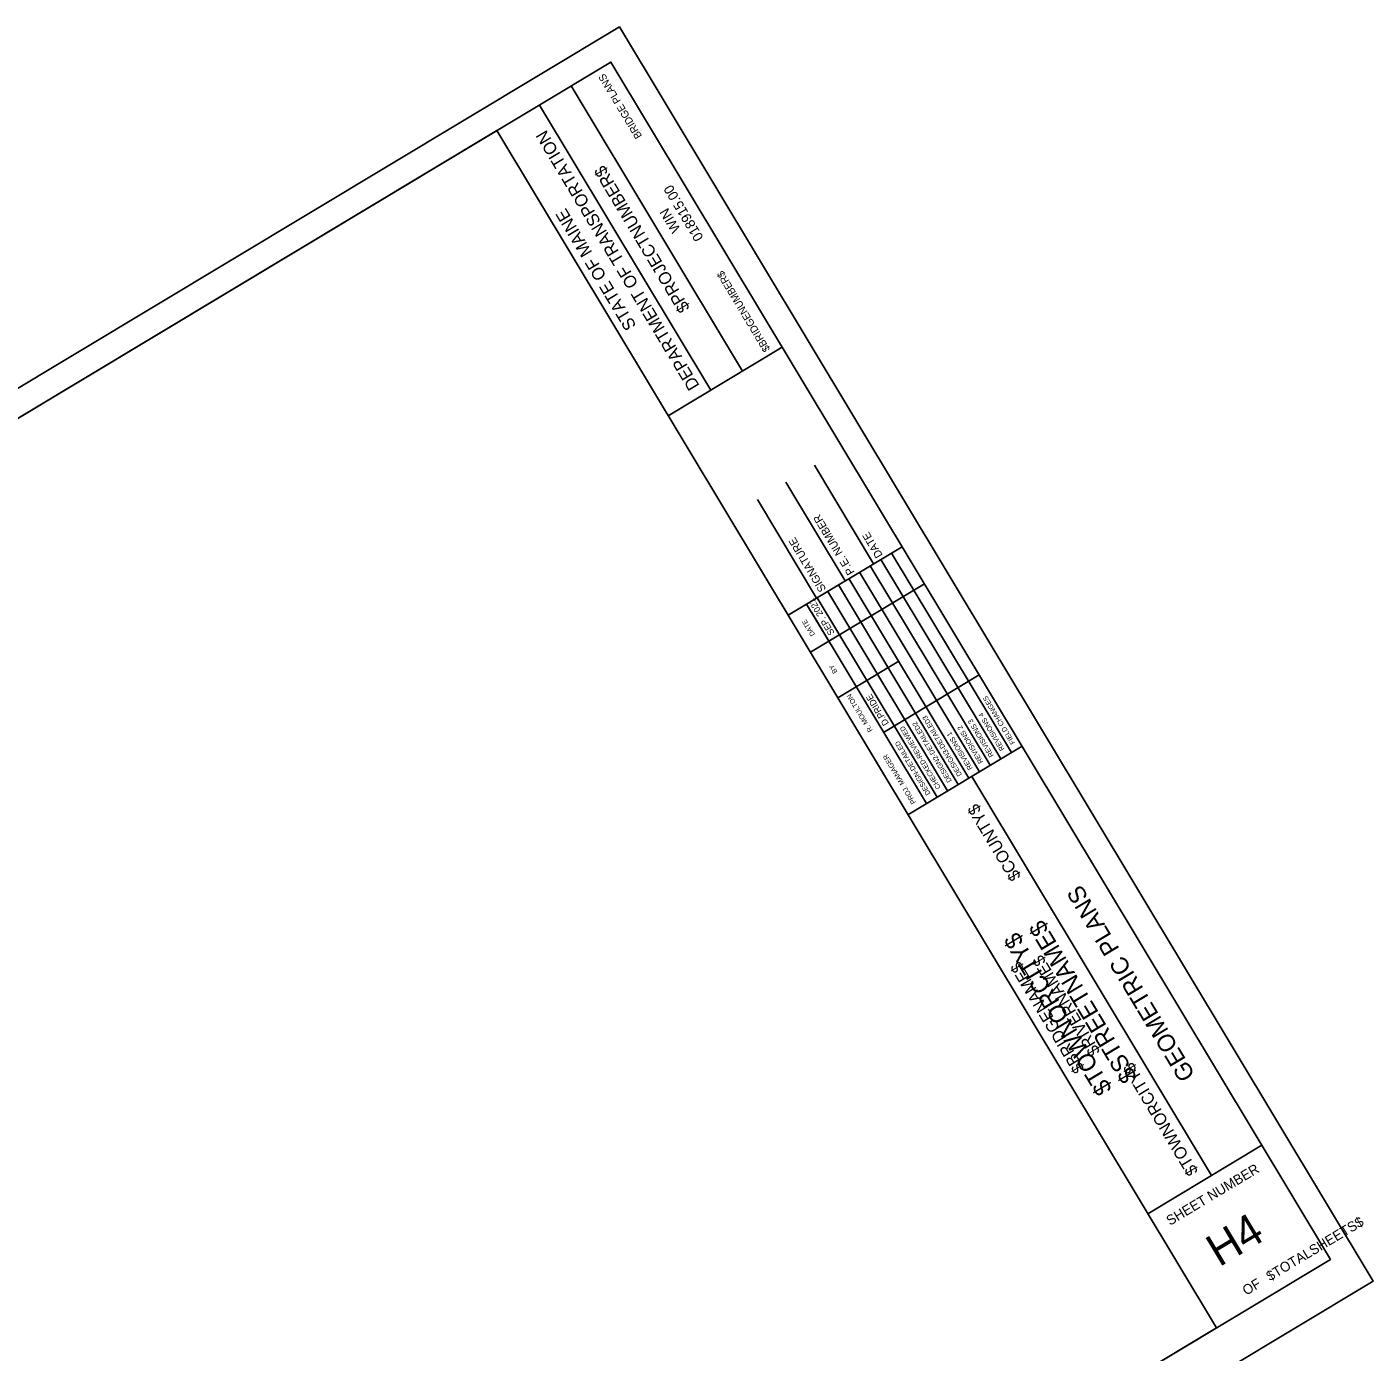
# Model space of a CAD drawing. Extents: x 1743892 to 1744904, y 462604 to 463513.
# Drawn here: x 1744398 to 1744904, y 463015 to 463513 of the extents above; entities that cross this region are included whole.
import ezdxf

# ---------------------------------------------------------------- set-up
doc = ezdxf.new("R2010")
doc.units = 0
for name, color, linetype in [('ANNOTATION', 7, 'Continuous'), ('D_Roadway_Centerline_Flags', 7, 'Continuous'), ('DIMENSIONS', 7, 'Continuous'), ('M_Fencing', 7, 'Continuous'), ('M_Misc_MiscItems', 7, 'Continuous')]:
    doc.layers.add(name, color=color, linetype=linetype)

msp = doc.modelspace()

# ---------------------------------------------------------------- linework, layer by layer
at = {"layer": 'DIMENSIONS'}
for p, q in [((1744667.22, 463384.05), (1744602.84, 463491.19)), ((1744655.24, 463376.85), (1744590.86, 463483.99)), ((1744845.27, 463024.39), (1744574.87, 463474.4)), ((1744639.27, 463367.24), (1744682.13, 463392.98)), ((1744716.46, 463311.58), (1744694.19, 463348.64)), ((1744705.74, 463305.14), (1744683.47, 463342.21)), ((1744695.03, 463298.71), (1744672.76, 463335.77)), ((1744684.31, 463292.27), (1744727.17, 463318.02)), ((1744729.38, 463217.27), (1744772.24, 463243.02)), ((1744843.47, 463081.66), (1744753.34, 463231.66)), ((1744819.51, 463067.26), (1744862.37, 463093.01))]:
    msp.add_line(p, q, dxfattribs=at)
msp.add_lwpolyline([(1743932, 463088.13), (1744617.73, 463500.16), (1744888.13, 463050.14), (1744202.39, 462638.11)], close=True, dxfattribs=at)
for points in [[(1744764.25, 463238.24), (1744719.19, 463313.22)], [(1744768.24, 463240.63), (1744723.18, 463315.62)], [(1744756.26, 463233.44), (1744711.2, 463308.43)], [(1744760.25, 463235.84), (1744715.2, 463310.83)], [(1744692.68, 463278.34), (1744735.54, 463304.09)], [(1744748.28, 463228.64), (1744703.22, 463303.63)], [(1744752.27, 463231.04), (1744707.21, 463306.03)], [(1744740.29, 463223.84), (1744695.23, 463298.83)], [(1744699.22, 463301.23), (1744744.28, 463226.24)], [(1744699.6, 463282.5), (1744691.23, 463296.43)], [(1744736.3, 463221.44), (1744693.06, 463293.4)], [(1744709.9, 463265.36), (1744725.88, 463274.95)], [(1744720.2, 463248.21), (1744756.14, 463269.81)], [(1744702.98, 463261.2), (1744709.91, 463265.36)]]:
    msp.add_lwpolyline(points, dxfattribs=at)
at = {"layer": 'M_Fencing'}
msp.add_lwpolyline([(1744175.59, 462604.16), (1744904.18, 463041.94), (1744620.91, 463513.38), (1743892.31, 463075.6)], close=True, dxfattribs=at)
at = {"layer": 'M_Misc_MiscItems'}
msp.add_lwpolyline([(1743932, 463088.13), (1744574.87, 463474.4), (1744845.27, 463024.39), (1744202.39, 462638.11)], close=True, dxfattribs=at)

# ---------------------------------------------------------------- texts
at = {"layer": 'ANNOTATION'}
for s, height, p in [('BRIDGE PLANS', 2.795, (1744629.51, 463472.38)), ('$BRIDGENUMBER$', 2.795, (1744677.66, 463392.26)), ('$COUNTY$', 4.536, (1744772.02, 463194.07)), ('$BRIDGENAME$', 4.5358, (1744795.92, 463121.73)), ('$RIVERNAME$', 4.5358, (1744801.78, 463128.26)), ('$TOWNORCITY$', 4.5358, (1744838.61, 463083.25))]:
    msp.add_text(s, height=height, rotation=121, dxfattribs=at).set_placement(p)
at = {"layer": 'D_Roadway_Centerline_Flags'}
for s, p in [('$STREETNAME$', (1744815.71, 463118.81)), ('$TOWNORCITY$', (1744806.31, 463114.21))]:
    msp.add_text(s, height=6.5214, rotation=121, dxfattribs=at).set_placement(p)
at = {"layer": 'DIMENSIONS'}
for s, height, rotation, p in [('DEPARTMENT OF TRANSPORTATION', 4.6588, 121, (1744651.18, 463378.54)), ('$PROJECTNUMBER$', 4.6588, 121, (1744647.57, 463407.71)), ('018915.00', 3.726, 121, (1744652.66, 463434.22)), ('STATE OF MAINE', 4.6588, 121, (1744627.43, 463401.06)), ('WIN', 3.726, 121, (1744644.01, 463437.37)), ('P.E. NUMBER', 2.9528, 121, (1744709.36, 463308.44)), ('DATE', 2.953, 121, (1744720, 463314.83)), ('SIGNATURE', 2.953, 121, (1744698.73, 463302.06)), ('SEP. 2021', 2.423, 121, (1744701.88, 463285.59)), ('DATE', 1.857, 121, (1744694.53, 463285.02)), ('BY', 1.857, 121, (1744702.95, 463271)), ('R. MOULTON', 1.864, 121, (1744716.17, 463249.01)), ('D.PRIDE', 2.423, 121, (1744722.28, 463251.63)), ('FIELD CHANGES', 1.8637, 121, (1744769.71, 463244.34)), ('DESIGN2-DETAILED2', 1.8637, 121, (1744745.91, 463230.05)), ('DESIGN3-DETAILED3', 1.8637, 121, (1744749.74, 463232.35)), ('REVISIONS 3', 1.8637, 121, (1744761.72, 463239.55)), ('REVISIONS 4', 1.8637, 121, (1744765.71, 463241.95)), ('CHECKED-REVIEWED', 1.8637, 121, (1744741.76, 463227.55)), ('REVISIONS 1', 1.8637, 121, (1744753.73, 463234.75)), ('REVISIONS 2', 1.8637, 121, (1744757.73, 463237.15)), ('DESIGN-DETAILED', 1.8637, 121, (1744737.92, 463225.25)), ('PROJ. MANAGER', 1.8637, 121, (1744732.43, 463221.94)), ('GEOMETRIC PLANS', 6.5214, 121, (1744837.51, 463119.49)), ('SHEET NUMBER', 3.7264, 31, (1744827.86, 463062.73)), ('H4', 12.097, 31, (1744846.36, 463047.11)), ('$TOTALSHEETS$', 3.7264, 31, (1744865.45, 463041.84)), ('OF', 3.726, 31, (1744856.49, 463036.46))]:
    msp.add_text(s, height=height, rotation=rotation, dxfattribs=at).set_placement(p)

doc.saveas('drawing.dxf')
